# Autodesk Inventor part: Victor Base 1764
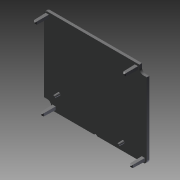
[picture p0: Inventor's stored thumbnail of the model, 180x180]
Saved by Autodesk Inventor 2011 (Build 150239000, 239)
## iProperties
Shininess: 64.0
Length Units: 11272
Angle Units: 11279
Time Units: 11290
Mass Units: 11286
Length Display Precision: 3
Angle Display Precision: 2
Compacted: True
Part Number: Victor Base 1764
Document SubType Name: Modeling
Created: 2007-01
Designer: uidk0133
Density: 1 g/cm^3
Density: 0.0
Volumn: 0.0
Area: 0.0
PropertySet Name: Model Information
Control State: 0
Master: False
Checked Out: False
Translation Standard: STEP AP203
File Name: V883-003 RevH.stp
Preprocessor: THINKDESIGN
Postprocessor: Build: Release: 6 RTM Build: 90b - Date: Tue 09/24/2002
Sent Units: INCHES
Uncertainty: 0.0
Author: uidk0133
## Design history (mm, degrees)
feature "Base1"
body "Solid1"
